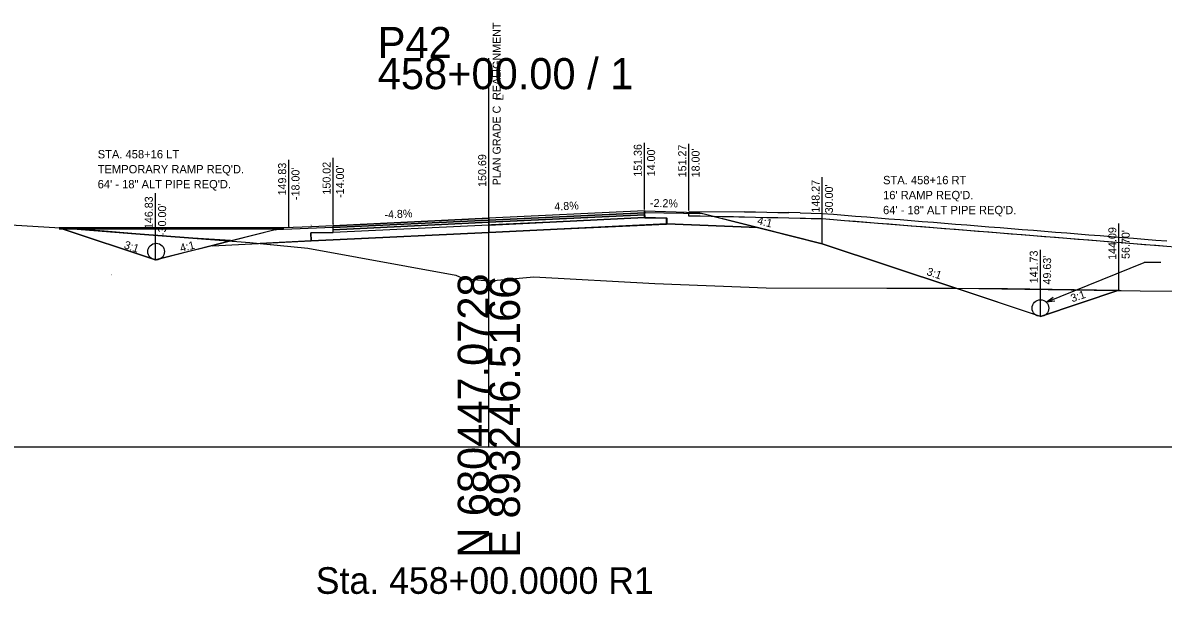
# Model space of a CAD drawing. Extents: x -26 to 4303, y -13 to 10775.
# Drawn here: x 108.1 to 210.7, y 6486.7 to 6538.2 of the extents above; entities that cross this region are included whole.
import ezdxf

# ---------------------------------------------------------------- set-up
doc = ezdxf.new("R2010")
doc.units = 0
for name, color, linetype in [('_CIVIL_CONSTRUCTION', 7, 'Continuous'), ('ASHPALT_12_5MM1', 7, 'Continuous'), ('CONST_DCH', 7, 'Continuous'), ('CONST_LV3', 7, 'Continuous'), ('Default', 7, 'Continuous'), ('Draft_XS_Text', 7, 'Continuous'), ('DTM_CORRIDOR', 7, 'Continuous'), ('DTM_P_FINISHED_GRADE', 7, 'Continuous'), ('DTM_TEMP_DROP', 7, 'Continuous'), ('DTM_X_GROUND', 7, 'Continuous'), ('SLOPE_STAKES_FILL', 7, 'Continuous'), ('X_PROFILES_1', 7, 'Continuous'), ('X_ROW', 7, 'Continuous'), ('XS_CELL', 7, 'Continuous'), ('XS_P_ASPHALT', 7, 'Continuous'), ('XS_P_DR_GRAVEL', 7, 'Continuous'), ('XS_P_DRAINAGE', 7, 'Continuous'), ('XS_P_GROUND', 7, 'Continuous'), ('XS_P_SUBGRADE_GRANULAR', 7, 'Continuous'), ('XS_P_SUBGRADE_MILLING', 7, 'Continuous'), ('XS_P_TX_CLEARZONE', 7, 'Continuous'), ('XS_P_TX_FS_BS', 7, 'Continuous'), ('XS_SHEET_EW_TX_AREA', 7, 'Continuous')]:
    doc.layers.add(name, color=color, linetype=linetype)

msp = doc.modelspace()

# ---------------------------------------------------------------- linework, layer by layer
for points in [[(136, 6519.73), (150, 6520.4), (150, 6520.21), (150, 6520.21), (136, 6519.54), (136, 6519.54), (136, 6519.54), (136, 6519.73), (136, 6519.73)], [(150, 6520.4), (150, 6520.4), (150, 6520.21), (150, 6520.21), (150, 6520.21), (164, 6520.88), (164, 6520.88), (164, 6521.07), (150, 6520.4)]]:
    msp.add_lwpolyline(points)
at = {"layer": 'ASHPALT_12_5MM1'}
for p, q in [((164, 6521.24), (150, 6520.57)), ((164, 6521.24), (164, 6521.07)), ((150, 6520.57), (136, 6519.89)), ((136, 6519.73), (136, 6519.87))]:
    msp.add_line(p, q, dxfattribs=at)
at = {"layer": 'CONST_LV3'}
for points in [[(180, 6518.27), (180, 6518.27), (174.16, 6519.73)], [(125.1, 6518.1), (120, 6516.83)]]:
    msp.add_lwpolyline(points, dxfattribs=at)
at = {"layer": 'Default'}
for points in [[(150, 6520.57), (150, 6520.57), (150, 6520.4), (150, 6520.4), (150, 6520.4), (164, 6521.07), (164, 6521.07), (164, 6521.24), (150, 6520.57)], [(136, 6519.89), (150, 6520.57), (150, 6520.4), (150, 6520.4), (136, 6519.73), (136, 6519.73), (136, 6519.73), (136, 6519.89), (136, 6519.89)]]:
    msp.add_lwpolyline(points, dxfattribs=at)
at = {"layer": 'DTM_P_FINISHED_GRADE'}
for p, q in [((173, 6521.16), (174, 6521.14)), ((174, 6521.14), (175, 6521.12)), ((175, 6521.12), (176, 6521.1)), ((176, 6521.1), (177, 6521.08)), ((178, 6521.05), (179, 6521.03)), ((179, 6521.03), (180, 6521.01)), ((180, 6521.01), (181, 6520.93)), ((181, 6520.93), (182, 6520.85)), ((182, 6520.85), (183, 6520.77)), ((183, 6520.77), (184, 6520.69)), ((184, 6520.69), (185, 6520.61)), ((185, 6520.61), (186, 6520.53)), ((186, 6520.53), (187, 6520.45)), ((187, 6520.45), (188, 6520.37)), ((188, 6520.37), (189, 6520.29)), ((189, 6520.29), (190, 6520.21)), ((190, 6520.21), (191, 6520.13)), ((191, 6520.13), (192, 6520.05)), ((192, 6520.05), (193, 6519.97)), ((193, 6519.97), (194, 6519.89)), ((194, 6519.89), (195, 6519.81)), ((195, 6519.81), (196, 6519.73)), ((196, 6519.73), (197, 6519.65)), ((197, 6519.65), (198, 6519.57)), ((198, 6519.57), (199, 6519.49)), ((199, 6519.49), (200, 6519.41)), ((200, 6519.41), (201, 6519.33)), ((201, 6519.33), (202, 6519.25)), ((202, 6519.25), (203, 6519.17)), ((203, 6519.17), (204, 6519.09)), ((204, 6519.09), (205, 6519.01)), ((205, 6519.01), (206, 6518.93)), ((206, 6518.93), (207, 6518.85)), ((207, 6518.85), (208, 6518.77)), ((208, 6518.77), (209, 6518.69)), ((209, 6518.69), (210, 6518.61)), ((210, 6518.61), (211, 6518.53))]:
    msp.add_line(p, q, dxfattribs=at)
at = {"layer": 'DTM_X_GROUND'}
msp.add_lwpolyline([(105.46, 6520.07), (110.94, 6519.73), (112.56, 6519.62), (118.22, 6519.18), (128.48, 6518.4), (133.7, 6517.87), (147.02, 6515.45), (147.69, 6515.14), (149.96, 6514.93), (150.42, 6514.98), (154.05, 6515.3), (164.93, 6514.69), (174.96, 6514.31), (196.66, 6514.26), (208.61, 6514.05), (251.67, 6513.69), (300, 6513.52)], dxfattribs=at)
at = {"layer": 'X_ROW'}
for p, q in [((164, 6521.07), (164, 6521.24)), ((164, 6521.24), (168.73, 6521.09)), ((169.24, 6520.96), (168.73, 6521.09)), ((169.26, 6520.96), (168.73, 6521.09)), ((164.09, 6521.07), (164, 6521.07)), ((169.26, 6520.96), (164, 6521.07)), ((169.24, 6520.96), (164.09, 6521.07)), ((136, 6519.73), (130.76, 6519.52)), ((130.76, 6519.52), (131.56, 6519.72)), ((134.04, 6519.81), (131.56, 6519.72)), ((136, 6519.89), (134.04, 6519.81)), ((136, 6519.73), (136, 6519.89)), ((136, 6519.73), (136, 6519.73))]:
    msp.add_line(p, q, dxfattribs=at)
for points in [[(165.96, 6520.04), (165.99, 6520.05), (165.99, 6520.58), (165.98, 6520.59), (164.03, 6520.62), (163.99, 6520.62), (150.25, 6519.97), (149.99, 6519.96), (150, 6519.31), (150, 6519.29), (150.25, 6519.31), (164, 6519.95), (165.96, 6520.04)], [(134, 6518.53), (136, 6518.62), (136, 6518.62), (150, 6519.29), (150, 6519.29), (150, 6519.96), (136, 6519.29), (136, 6519.29), (133.99, 6519.25), (133.99, 6519.25), (134, 6518.53), (134, 6518.53), (134, 6518.53)]]:
    msp.add_lwpolyline(points, dxfattribs=at)
at = {"layer": 'XS_CELL'}
for p, q in [((150, 6500), (150, 6535)), ((0, 6500), (150, 6500)), ((150, 6500), (300, 6500))]:
    msp.add_line(p, q, dxfattribs=at)
at = {"layer": 'XS_P_ASPHALT'}
msp.add_lwpolyline([(166, 6520.06), (166.01, 6520.59), (164, 6520.63), (150, 6519.96), (150, 6519.29), (166, 6520.06)], dxfattribs=at)
at = {"layer": 'XS_P_DR_GRAVEL'}
for p, q in [((173, 6521.16), (168, 6521.11)), ((168, 6520.77), (168, 6521.11)), ((173, 6521.16), (174, 6521.14)), ((174, 6521.14), (175, 6521.12)), ((175, 6521.12), (176, 6521.1)), ((176, 6521.1), (177, 6521.08)), ((178, 6521.05), (177, 6521.08)), ((169, 6520.75), (168, 6520.77)), ((170, 6520.73), (169, 6520.75)), ((171, 6520.71), (170, 6520.73)), ((170, 6520.73), (170, 6520.73)), ((172, 6520.69), (171, 6520.71)), ((173, 6520.66), (172, 6520.69)), ((172, 6520.69), (172, 6520.69)), ((174, 6520.64), (173, 6520.66)), ((175, 6520.62), (174, 6520.64)), ((176, 6520.6), (175, 6520.62)), ((177, 6520.58), (176, 6520.6)), ((178, 6520.55), (177, 6520.58)), ((178, 6521.05), (179, 6521.03)), ((179, 6520.53), (178, 6520.55)), ((179, 6521.03), (180, 6521.01)), ((180, 6520.51), (179, 6520.53)), ((180, 6521.01), (181, 6520.93)), ((181, 6520.43), (180, 6520.51)), ((181, 6520.93), (182, 6520.85)), ((182, 6520.35), (181, 6520.43)), ((182, 6520.85), (183, 6520.77)), ((183, 6520.27), (182, 6520.35)), ((183, 6520.77), (184, 6520.69)), ((184, 6520.19), (183, 6520.27)), ((184, 6520.69), (185, 6520.61)), ((185, 6520.11), (184, 6520.19)), ((185, 6520.61), (186, 6520.53)), ((186, 6520.03), (185, 6520.11)), ((186, 6520.53), (187, 6520.45)), ((187, 6520.45), (188, 6520.37)), ((188, 6520.37), (189, 6520.29)), ((189, 6520.29), (190, 6520.21)), ((190, 6520.21), (191, 6520.13)), ((191, 6520.13), (192, 6520.05)), ((192, 6520.05), (193, 6519.97)), ((131.56, 6519.72), (111.35, 6519.71)), ((131.56, 6519.59), (111.35, 6519.58)), ((187, 6519.95), (186, 6520.03)), ((188, 6519.87), (187, 6519.95)), ((189, 6519.79), (188, 6519.87)), ((190, 6519.71), (189, 6519.79)), ((191, 6519.63), (190, 6519.71)), ((192, 6519.55), (191, 6519.63)), ((193, 6519.47), (192, 6519.55)), ((193, 6519.97), (194, 6519.89)), ((194, 6519.39), (193, 6519.47)), ((194, 6519.89), (195, 6519.81)), ((195, 6519.31), (194, 6519.39)), ((195, 6519.81), (196, 6519.73)), ((196, 6519.23), (195, 6519.31)), ((196, 6519.73), (197, 6519.65)), ((197, 6519.15), (196, 6519.23)), ((197, 6519.65), (198, 6519.57)), ((198, 6519.07), (197, 6519.15)), ((198, 6519.57), (199, 6519.49)), ((199, 6518.99), (198, 6519.07)), ((199, 6519.49), (200, 6519.41)), ((200, 6519.41), (201, 6519.33)), ((201, 6519.33), (202, 6519.25)), ((202, 6519.25), (203, 6519.17)), ((203, 6519.17), (204, 6519.09)), ((204, 6519.09), (205, 6519.01)), ((200, 6518.91), (199, 6518.99)), ((201, 6518.83), (200, 6518.91)), ((202, 6518.75), (201, 6518.83)), ((203, 6518.67), (202, 6518.75)), ((204, 6518.59), (203, 6518.67)), ((205, 6518.51), (204, 6518.59)), ((205, 6519.01), (206, 6518.93)), ((206, 6518.43), (205, 6518.51)), ((206, 6518.93), (207, 6518.85)), ((207, 6518.35), (206, 6518.43)), ((207, 6518.85), (208, 6518.77)), ((208, 6518.27), (207, 6518.35)), ((208, 6518.77), (209, 6518.69)), ((209, 6518.19), (208, 6518.27)), ((209, 6518.69), (210, 6518.61)), ((210, 6518.11), (209, 6518.19)), ((210, 6518.61), (211, 6518.53)), ((211, 6518.03), (210, 6518.11))]:
    msp.add_line(p, q, dxfattribs=at)
at = {"layer": 'XS_P_DRAINAGE'}
for p in [(200.16, 6513.01), (210.47, 6516.6)]:
    msp.add_line(p, (208.97, 6516.6), dxfattribs=at)
msp.add_lwpolyline([(200.93, 6513.12), (200.16, 6513.01), (200.79, 6513.47)], dxfattribs=at)
for centre in [(120.06, 6517.57), (199.63, 6512.48)]:
    msp.add_circle(centre, 0.75, dxfattribs=at)
at = {"layer": 'XS_P_GROUND'}
for points in [[(199.63, 6511.73), (180, 6518.27), (180, 6518.27), (180, 6518.27), (169.24, 6520.96)], [(120, 6516.83), (111.35, 6519.71)], [(130.76, 6519.52), (120, 6516.83)], [(199.63, 6511.73), (206.7, 6514.09)]]:
    msp.add_lwpolyline(points, dxfattribs=at)
at = {"layer": 'XS_P_SUBGRADE_GRANULAR'}
for points in [[(166, 6520.06), (150, 6519.29), (150, 6519.29)], [(136, 6518.62), (136, 6518.62), (150, 6519.29)]]:
    msp.add_lwpolyline(points, dxfattribs=at)
at = {"layer": 'XS_P_SUBGRADE_MILLING'}
for points in [[(136, 6519.54), (150, 6520.21), (150, 6519.96), (150, 6519.96), (136, 6519.29), (136, 6519.29), (136, 6519.29), (136, 6519.54), (136, 6519.54)], [(150, 6520.21), (150, 6520.21), (150, 6519.96), (150, 6519.96), (150, 6519.96), (164, 6520.63), (164, 6520.63), (164, 6520.88), (150, 6520.21)]]:
    msp.add_lwpolyline(points, dxfattribs=at)
at = {"layer": 'XS_P_TX_CLEARZONE'}
for p, q in [((164, 6521.36), (164, 6527.36)), ((164, 6521.36), (164, 6527.36)), ((164, 6521.36), (164, 6527.36)), ((168, 6521.27), (168, 6527.27)), ((168, 6521.27), (168, 6527.27)), ((168, 6521.27), (168, 6527.27)), ((150, 6520.69), (150, 6526.69)), ((150, 6520.69), (150, 6526.69)), ((132, 6519.83), (132, 6525.83)), ((132, 6519.83), (132, 6525.83)), ((136, 6520.02), (136, 6526.02)), ((136, 6520.02), (136, 6526.02)), ((136, 6520.02), (136, 6526.02)), ((180, 6518.27), (180, 6524.27)), ((180, 6518.27), (180, 6524.27)), ((180, 6518.27), (180, 6524.27)), ((120, 6516.83), (120, 6522.83)), ((120, 6516.83), (120, 6522.83)), ((206.7, 6514.09), (206.7, 6520.09)), ((206.7, 6514.09), (206.7, 6520.09)), ((199.63, 6511.73), (199.63, 6517.73)), ((199.63, 6511.73), (199.63, 6517.73))]:
    msp.add_line(p, q, dxfattribs=at)
at = {"layer": 'XS_SHEET_EW_TX_AREA'}
for points in [[(129.42, 6518.31), (133.7, 6517.87), (147.02, 6515.45), (147.69, 6515.14), (149.96, 6514.93), (150.42, 6514.98), (154.05, 6515.3), (164.93, 6514.69), (174.96, 6514.31), (192.01, 6514.27), (180, 6518.27), (174.16, 6519.73), (166, 6520.06), (150, 6519.29), (136, 6518.62), (134, 6518.53)], [(174.16, 6519.73), (169.24, 6520.96), (164, 6521.07), (164.03, 6520.62), (166.01, 6520.59), (166, 6520.06)], [(170.27, 6520.73), (180, 6518.27), (192.01, 6514.27), (208.61, 6514.05), (230.14, 6513.87), (251.67, 6513.69), (265.78, 6513.63), (239, 6515.79), (214, 6517.79), (193, 6519.47), (182, 6520.35), (180, 6520.51), (177, 6520.58), (172.5, 6520.68)], [(120, 6516.83), (126.76, 6518.57), (123.35, 6518.79), (118.22, 6519.18), (115.39, 6519.4), (112.56, 6519.62), (111.35, 6519.71)], [(136, 6519.29), (136, 6519.73), (130.76, 6519.52), (125.1, 6518.1), (134, 6518.53), (133.99, 6519.25)], [(192.01, 6514.27), (196.66, 6514.26), (206.7, 6514.09), (199.63, 6511.73)]]:
    msp.add_lwpolyline(points, close=True, dxfattribs=at)

# ---------------------------------------------------------------- texts
at = {"layer": '_CIVIL_CONSTRUCTION'}
for p in [(163.96, 6521.3), (163.96, 6521.3), (163.96, 6521.3), (163.96, 6521.3), (135.96, 6519.96), (135.96, 6519.96), (135.96, 6519.96), (149.96, 6520.63), (165.97, 6520.53), (168.9, 6520.91), (168.9, 6520.91), (168.9, 6520.91), (131.02, 6519.56), (131.02, 6519.56), (133.95, 6519.19), (133.96, 6519.88), (133.96, 6519.86), (133.96, 6519.86)]:
    msp.add_text('X', height=0.12, dxfattribs=at).set_placement(p)
at = {"layer": 'CONST_DCH'}
for p in [(115.98, 6515.44), (199.59, 6511.67), (199.59, 6511.67)]:
    msp.add_text('X', height=0.12, dxfattribs=at).set_placement(p)
at = {"layer": 'Draft_XS_Text'}
msp.add_text('Sta. 458+00.0000 R1', height=2.4, dxfattribs=at).set_placement((134.42, 6486.75))
at = {"layer": 'DTM_CORRIDOR'}
msp.add_text('X', height=0.12, dxfattribs=at).set_placement((206.67, 6514.03))
at = {"layer": 'DTM_TEMP_DROP'}
for p in [(167.96, 6521.21), (167.96, 6521.21), (167.96, 6521.21), (131.96, 6519.8), (131.96, 6519.77)]:
    msp.add_text('X', height=0.12, dxfattribs=at).set_placement(p)
at = {"layer": 'SLOPE_STAKES_FILL'}
for p in [(179.96, 6518.21), (119.96, 6516.77)]:
    msp.add_text('X', height=0.12, dxfattribs=at).set_placement(p)
at = {"layer": 'X_PROFILES_1'}
msp.add_text('X', height=0.12, dxfattribs=at).set_placement((169.21, 6520.9))
at = {"layer": 'XS_CELL'}
for s, p in [('P42', (140, 6535)), ('458+00.00 / 1', (140, 6532.2))]:
    msp.add_text(s, height=2.8, dxfattribs=at).set_placement(p)
for s, p in [('N 680447.0728', (150, 6490)), ('E 893246.5166', (152.8, 6490))]:
    msp.add_text(s, height=2.8, rotation=90, dxfattribs=at).set_placement(p)
at = {"layer": 'XS_P_DRAINAGE'}
for s, p in [('STA. 458+16 LT', (114.8, 6525.97)), ("TEMPORARY RAMP REQ'D.", (114.8, 6524.62)), ('STA. 458+16 RT', (185.47, 6523.64)), ('64\' - 18" ALT PIPE REQ\'D.', (114.8, 6523.27)), ("16' RAMP REQ'D.", (185.47, 6522.29)), ('64\' - 18" ALT PIPE REQ\'D.', (185.47, 6520.94))]:
    msp.add_text(s, height=0.75, dxfattribs=at).set_placement(p)
at = {"layer": 'XS_P_TX_CLEARZONE'}
for s, p in [('PLAN GRADE C  REALIGNMENT', (151.06, 6523.54)), ('L', (151.31, 6531.19)), ('150.69', (149.76, 6523.4)), ('150.69', (149.76, 6523.4)), ('151.36', (163.76, 6524.31)), ('151.36', (163.76, 6524.31)), ('151.36', (163.76, 6524.31)), ("14.00'", (164.96, 6524.35)), ("14.00'", (164.96, 6524.35)), ("14.00'", (164.96, 6524.35)), ('151.27', (167.76, 6524.26)), ('151.27', (167.76, 6524.26)), ('151.27', (167.76, 6524.26)), ("18.00'", (168.96, 6524.26)), ("18.00'", (168.96, 6524.26)), ("18.00'", (168.96, 6524.26)), ('149.83', (131.76, 6522.63)), ('149.83', (131.76, 6522.63)), ('150.02', (135.76, 6522.71)), ('150.02', (135.76, 6522.71)), ('150.02', (135.76, 6522.71)), ("-14.00'", (136.96, 6522.41)), ("-14.00'", (136.96, 6522.41)), ("-14.00'", (136.96, 6522.41)), ("-18.00'", (132.96, 6522.22)), ("-18.00'", (132.96, 6522.22)), ('148.27', (179.76, 6521.08)), ('148.27', (179.76, 6521.08)), ('148.27', (179.76, 6521.08)), ("30.00'", (180.96, 6521.02)), ("30.00'", (180.96, 6521.02)), ("30.00'", (180.96, 6521.02)), ('146.83', (119.76, 6519.6)), ('146.83', (119.76, 6519.6)), ("-30.00'", (120.96, 6518.98)), ("-30.00'", (120.96, 6518.98)), ('144.09', (206.46, 6516.83)), ('144.09', (206.46, 6516.83)), ("56.70'", (207.66, 6516.91)), ("56.70'", (207.66, 6516.91)), ('141.73', (199.39, 6514.72)), ('141.73', (199.39, 6514.72)), ("49.63'", (200.59, 6514.61)), ("49.63'", (200.59, 6514.61))]:
    msp.add_text(s, height=0.72, rotation=90, dxfattribs=at).set_placement(p)
at = {"layer": 'XS_P_TX_FS_BS'}
for s, rotation, p in [('-2.2%', 358.7209, (164.49, 6521.6)), ('-4.8%', 2.7481, (140.62, 6520.54)), ('4.8%', 2.7481, (155.91, 6521.27)), ('4:1', 345.9638, (174.1, 6520.06)), ('3:1', 341.5668, (117.11, 6517.89)), ('4:1', 14.1908, (122.3, 6517.52)), ('3:1', 341.5668, (189.33, 6515.48)), ('3:1', 18.4349, (202.49, 6513))]:
    msp.add_text(s, height=0.72, rotation=rotation, dxfattribs=at).set_placement(p)

doc.saveas('drawing.dxf')
